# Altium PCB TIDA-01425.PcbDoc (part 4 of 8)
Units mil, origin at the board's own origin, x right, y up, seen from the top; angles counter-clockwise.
Board outline 7000 x 3600 mil, 6 copper layers (Layer 1 - Top Layer, Layer 2 - GND, Layer 3 - Signal / PWR, Layer 4 - Signal / PWR, Layer 5 - PWR, Layer 6 - Bottom Layer), stack 60.4 mil thick; 495 components, 307 nets, 2058 pads, 1870 vias.
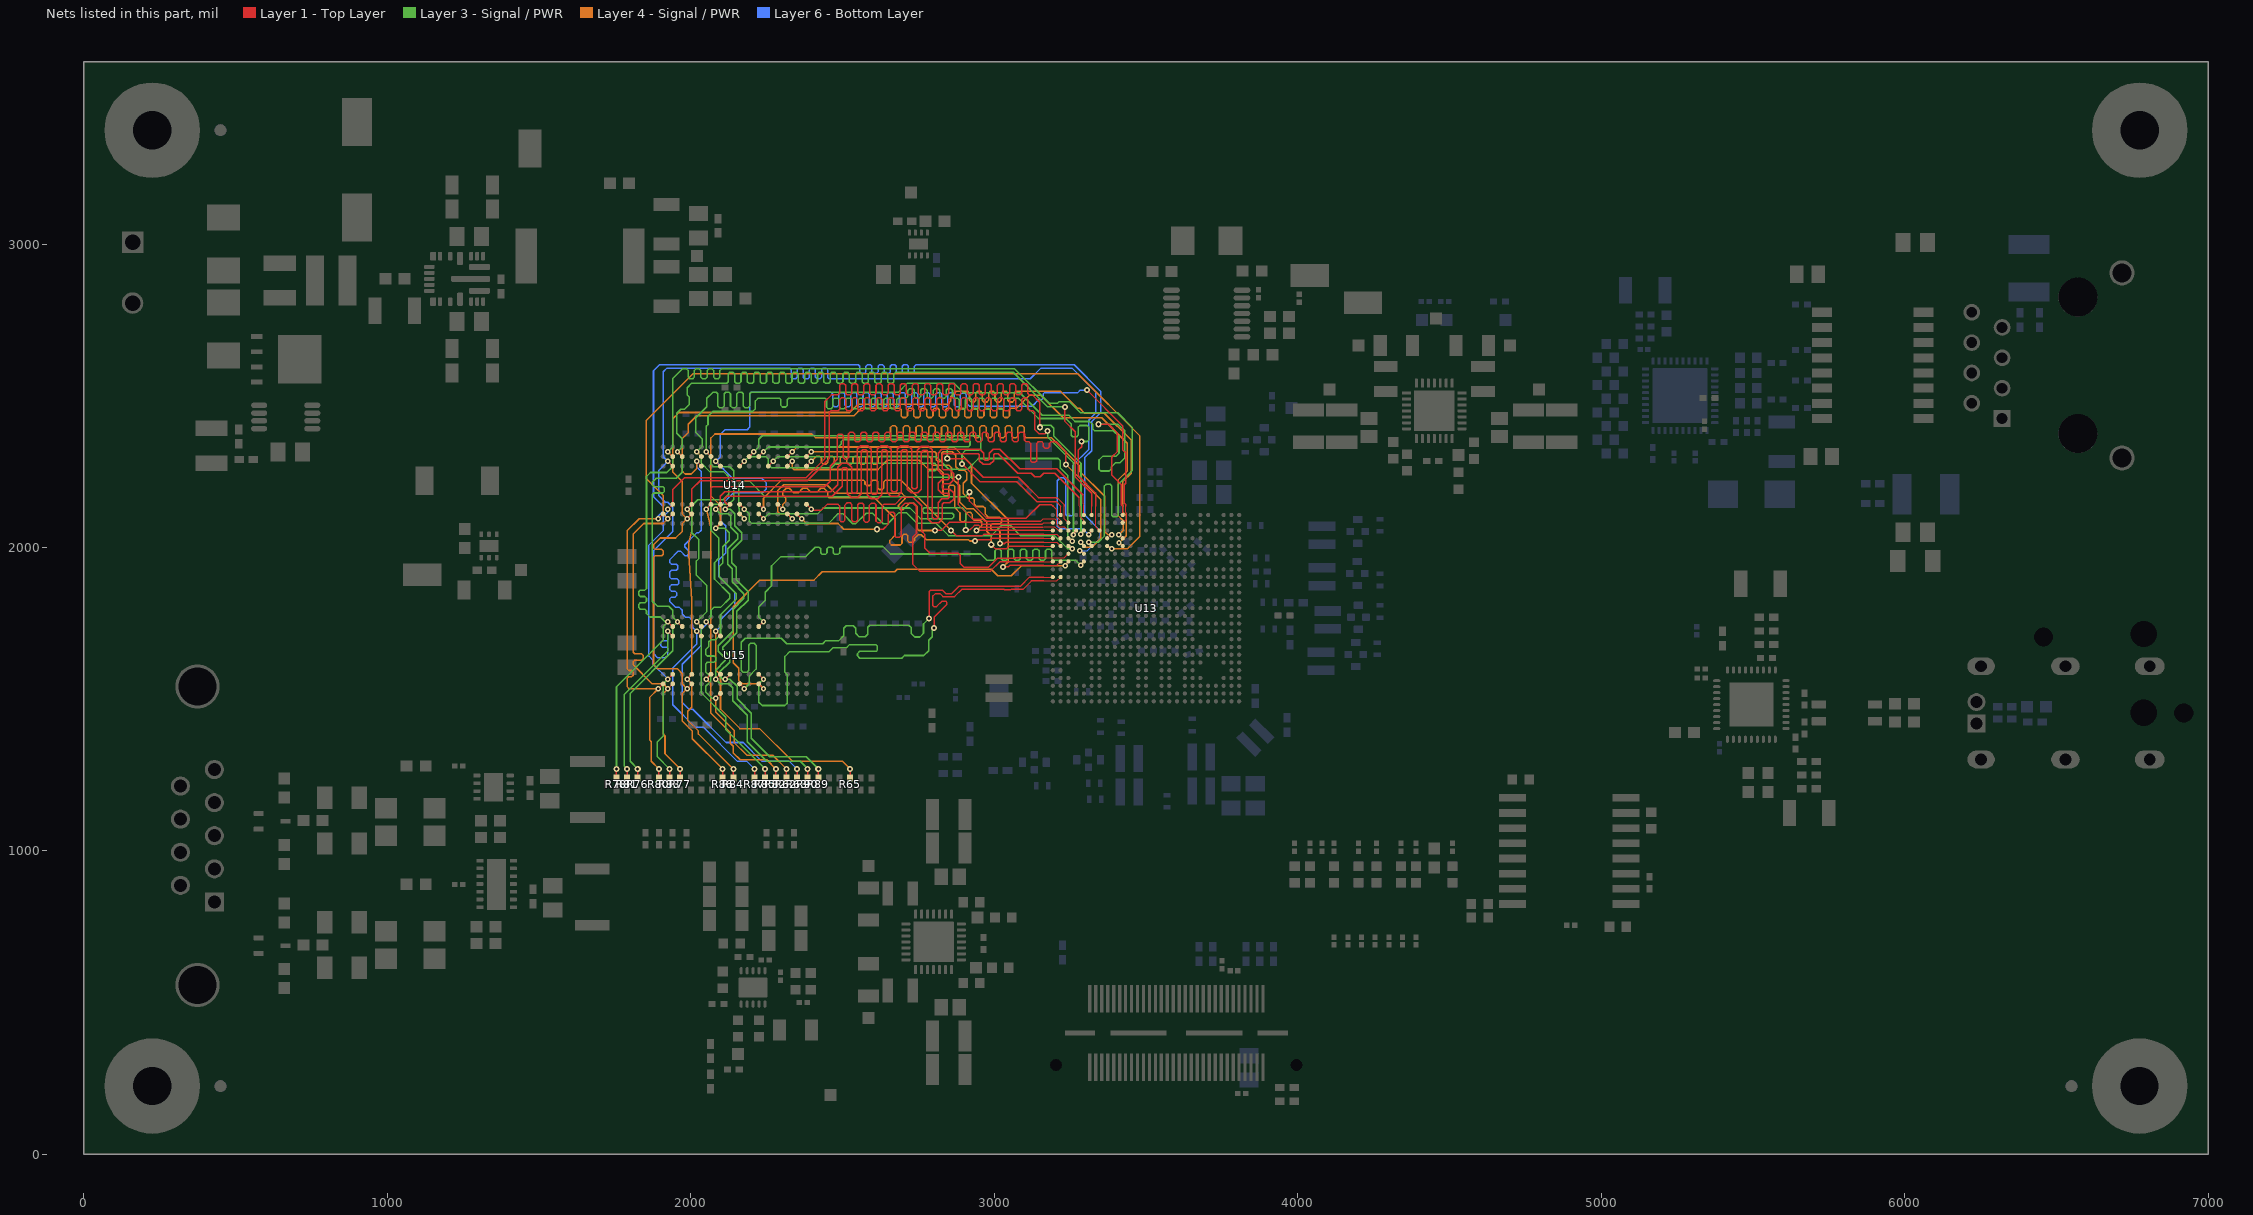
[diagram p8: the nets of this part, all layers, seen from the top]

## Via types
v1: diameter 20, hole 10, Layer 1 - Top Layer to Layer 6 - Bottom Layer, tented both sides, 1119 vias
v2: diameter 20, hole 9.99, Layer 1 - Top Layer to Layer 6 - Bottom Layer, tented both sides, 298 vias
v3: diameter 18, hole 7.99, Layer 1 - Top Layer to Layer 6 - Bottom Layer, tented both sides, 203 vias
v4: diameter 18, hole 8, Layer 1 - Top Layer to Layer 6 - Bottom Layer, tented both sides, 177 vias
v5: diameter 19.68, hole 7.87, Layer 1 - Top Layer to Layer 6 - Bottom Layer, tented both sides, 41 vias
v6: diameter 20, hole 10, Layer 1 - Top Layer to Layer 6 - Bottom Layer, 27 vias
v7: diameter 19.68, hole 7.87, Layer 1 - Top Layer to Layer 6 - Bottom Layer, 5 vias

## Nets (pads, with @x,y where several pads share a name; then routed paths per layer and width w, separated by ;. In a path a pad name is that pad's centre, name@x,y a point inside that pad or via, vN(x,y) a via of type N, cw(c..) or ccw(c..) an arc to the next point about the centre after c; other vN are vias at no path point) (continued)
H_DDR1_A5: R76.1 U13.AE20 U14.P2 U15.P2 | length 4165
  Layer 1 - Top Layer w4: v4(1956.03,1755.22) U15.P2@1971.77,1739.49 ; v4(1956.03,2315.22) U14.P2@1971.77,2299.49 ; U13.AE20@3320.87,2107.09 3320.87,2136
  Layer 1 - Top Layer w5: R76.1@1825,1239.68 v1(1825,1270) ; v1(3233,2463) 3233,2415.5 3267,2381.5 3267,2232.15 3320.87,2178.28 3320.87,2136
  Layer 3 - Signal / PWR w5.25: v1(1825,1270) 1800,1294.99 1800,1519 1940.3,1659.3 1940.3,1739.49 v4(1956.03,1755.22) 1940.3,1770.95 1940.3,1793.06 1927.36,1806 1890,1806 1873,1823 1873,2174.24 1878.25,2179.49 1907.75,2179.49 1913,2184.74 1913,2195.24 1907.75,2200.49 1878.25,2200.49 1873,2205.74 1873,2214.99 1886.01,2228 1952,2228 1971.66,2247.66 1971.66,2279.65 1971.9,2279.89 1971.9,2299.35 v4(1956.03,2315.22) 1971.9,2331.09 1971.9,2358.53 1954,2376.43 1954,2442.17 1967.23,2455.4 1978.92,2455.4 1995.3,2471.78 1995.3,2495 1987.8,2502.5 1987.8,2526.5 2002.1,2540.8 2118.09,2540.8 2123.34,2546.05 2123.34,2571.95 2128.59,2577.2 2139.09,2577.2 2144.34,2571.95 2144.34,2546.05 2149.59,2540.8 2160.09,2540.8 2165.34,2546.05 2165.34,2571.95 2170.59,2577.2 2181.09,2577.2 2186.34,2571.95 2186.34,2546.05 2191.59,2540.8 2202.09,2540.8 2207.34,2546.05 2207.34,2571.95 2212.59,2577.2 2223.09,2577.2 2228.34,2571.95 2228.34,2546.05 2233.59,2540.8 2244.09,2540.8 2249.34,2546.05 2249.34,2571.95 2254.59,2577.2 2265.09,2577.2 2270.34,2571.95 2270.34,2546.05 2275.59,2540.8 2286.09,2540.8 2291.34,2546.05 2291.34,2571.95 2296.59,2577.2 2307.09,2577.2 2312.34,2571.95 2312.34,2546.05 2317.59,2540.8 2328.09,2540.8 2333.34,2546.05 2333.34,2571.95 2338.59,2577.2 2349.09,2577.2 2354.34,2571.95 2354.34,2546.05 2359.59,2540.8 2370.09,2540.8 2375.34,2546.05 2375.34,2571.95 2380.59,2577.2 2391.09,2577.2 2396.34,2571.95 2396.34,2546.05 2401.59,2540.8 2412.09,2540.8 2417.34,2546.05 2417.34,2571.95 2422.59,2577.2 2433.09,2577.2 2438.34,2571.95 2438.34,2546.05 2443.59,2540.8 2454.09,2540.8 2459.34,2546.05 2459.34,2571.95 2464.59,2577.2 2475.09,2577.2 2480.34,2571.95 2480.34,2546.05 2485.59,2540.8 2496.09,2540.8 2501.34,2546.05 2501.34,2571.95 2506.59,2577.2 2517.09,2577.2 2522.34,2571.95 2522.34,2546.05 2527.59,2540.8 2538.09,2540.8 2543.34,2546.05 2543.34,2571.95 2548.59,2577.2 2559.09,2577.2 2564.34,2571.95 2564.34,2546.05 2569.59,2540.8 2580.09,2540.8 2585.34,2546.05 2585.34,2571.95 2590.59,2577.2 2601.09,2577.2 2606.34,2571.95 2606.34,2546.05 2611.59,2540.8 2622.09,2540.8 2627.34,2546.05 2627.34,2571.95 2632.59,2577.2 2643.09,2577.2 2648.34,2571.95 2648.34,2546.05 2653.59,2540.8 2664.09,2540.8 2669.34,2546.05 2669.34,2571.95 2674.59,2577.2 3062.3,2577.2 3176.5,2463 v1(3233,2463)
H_DDR1_A6: R77.1 U13.AA18 U14.R8 U15.R8 | length 3724.2
  Layer 1 - Top Layer w4: v4(1924.54,1534.77) U15.R8@1940.28,1550.51 ; v4(1924.54,2094.77) U14.R8@1940.28,2110.51 ; U13.AA18@3372.05,2004.72 3377.68,2004.72 v3(3386.6,1995.8)
  Layer 1 - Top Layer w5: R77.1@1965,1239.68 v1(1965,1270)
  Layer 4 - Signal / PWR w5.25: v1(1965,1270) 1915,1319.99 1915,1380 1908.8,1386.2 1908.8,1519.03 v4(1924.54,1534.77) 1908.67,1550.64 1899.52,1550.64 1872.37,1550.63 1810,1613 1810,1623.25 1815.25,1628.5 1837.75,1628.5 1843,1633.75 1843,1644.25 1837.75,1649.5 1815.25,1649.5 1810,1654.75 1810,2043.99 1844.9,2078.89 1908.66,2078.89 v4(1924.54,2094.77) 1908.9,2110.41 1908.9,2171.1 1853.1,2226.9 1853.1,2418 2007.23,2572.13 3275.39,2572.13 3480,2367.52 3480,2037 3438.8,1995.8 v3(3386.6,1995.8)
H_DDR1_A7: R78.1 U13.AA20 U14.R2 U15.R2 | length 4115.6
  Layer 1 - Top Layer w4: v4(1924.54,1755.22) U15.R2@1940.28,1739.49 ; v4(1924.54,2315.22) U14.R2@1940.28,2299.49 ; v3(3310.7,2017.2) U13.AA20@3320.8,2004.8
  Layer 1 - Top Layer w5: R78.1@1755,1239.68 v1(1755,1270)
  Layer 3 - Signal / PWR w5.25: v1(1755,1270) 1755,1541 1908.9,1694.9 1908.9,1739.58 v4(1924.54,1755.22) 1915.14,1755.22 1899.51,1770.85 1865.15,1770.85 1854,1782 1854,1791.25 1848.75,1796.5 1833.25,1796.5 1828,1801.75 1828,1812.25 1833.25,1817.5 1848.75,1817.5 1854,1822.75 1854,1833.25 1848.75,1838.5 1833.25,1838.5 1828,1843.75 1828,1854.25 1833.25,1859.5 1848.75,1859.5 1854,1864.75 1854,2234 1867,2247 1920.99,2247 1940.17,2266.18 1940.17,2299.59 v4(1924.54,2315.22) 1940.4,2331.08 1940.4,2557.1 1971.65,2588.35 1985.62,2588.35 1990.87,2583.1 1990.87,2561.45 1996.12,2556.2 2006.62,2556.2 2011.87,2561.45 2011.87,2583.1 2017.12,2588.35 2027.62,2588.35 2032.87,2583.1 2032.87,2561.45 2038.12,2556.2 2048.62,2556.2 2053.87,2561.45 2053.87,2583.1 2059.12,2588.35 2069.62,2588.35 2074.87,2583.1 2074.87,2561.45 2080.12,2556.2 2090.62,2556.2 2095.87,2561.45 2095.87,2583.1 2101.12,2588.35 3067.85,2588.35 3180.9,2475.3 3208.1,2475.3 3213.2,2480.4 3247.6,2480.4 3284.4,2443.6 3407.19,2443.6 3454.1,2396.69 3454.1,2253 3408.4,2207.3 3408.4,2105.4 3403.7,2100.7 3392.45,2100.7 3387.2,2105.95 3387.2,2202.7 3381.9,2208 3368.6,2208 3363,2202.4 3363,2037.5 3342.7,2017.2 v3(3310.7,2017.2)
H_DDR1_A8: R80.1 U13.Y21 U14.T8 U15.T8 | length 4009.1
  Layer 1 - Top Layer w4: v4(1893.04,1534.77) U15.T8@1908.78,1550.51 ; v4(1893.04,2094.77) U14.T8@1908.78,2110.51 ; v3(3282.2,1988.7) U13.Y21@3295.2,1979.2
  Layer 1 - Top Layer w5: R80.1@1895,1239.68 v1(1895,1270)
  Layer 4 - Signal / PWR w5.25: v4(1893.04,2094.77) 1829.76,2094.77 1790,2055.01 1790,1599.76 1795.25,1594.51 1804.75,1594.51 1810,1589.26 1810,1578.76 1804.75,1573.51 1795.25,1573.51 1790,1568.26 1790,1542.01 1797.24,1534.77 v4(1893.04,1534.77) 1864.13,1505.86 1864.13,1365.87 1870,1360 1870,1294.99 v1(1895,1270)
  Layer 6 - Bottom Layer w4: v3(3282.2,1988.7) 3306.7,1988.7 3348.79,2030.79 3348.79,2056.21
  Layer 6 - Bottom Layer w5: v4(1893.04,2094.77) 1893.04,2104.33 1908.54,2119.83 1908.54,2135.46 1877,2167 1877,2582.4 1896.5,2601.9 2551.93,2601.9 2556.93,2596.9 2556.93,2578.4 2561.93,2573.4 2571.93,2573.4 2576.93,2578.4 2576.93,2596.9 2581.93,2601.9 2591.93,2601.9 2596.93,2596.9 2596.93,2578.4 2601.93,2573.4 2611.93,2573.4 2616.93,2578.4 2616.93,2596.9 2621.93,2601.9 2631.93,2601.9 2636.93,2596.9 2636.93,2578.4 2641.93,2573.4 2651.93,2573.4 2656.93,2578.4 2656.93,2596.9 2661.93,2601.9 2671.93,2601.9 2676.93,2596.9 2676.93,2578.4 2681.93,2573.4 2691.93,2573.4 2696.93,2578.4 2696.93,2596.9 2701.93,2601.9 2711.93,2601.9 2716.93,2596.9 2716.93,2578.4 2721.93,2573.4 2731.93,2573.4 2736.93,2578.4 2736.93,2596.9 2741.93,2601.9 3263.4,2601.9 3351,2514.3 3351,2445 3321,2415 3321,2319 3298,2296 3298,2107 3348.79,2056.21
H_DDR1_A9: R81.1 U13.AC20 U14.R3 U15.R3 | length 4335.4
  Layer 1 - Top Layer w4: v4(1924.54,1723.73) U15.R3@1940.28,1707.99 ; v4(1924.54,2283.73) U14.R3@1940.28,2267.99 ; v3(3310.8,2042.6) U13.AC20@3320.87,2055.91
  Layer 1 - Top Layer w5: R81.1@1790,1239.68 v1(1790,1270)
  Layer 3 - Signal / PWR w5.25: v1(1790,1270) 1780,1279.99 1780,1514.6 1924.54,1659.14 v4(1924.54,1723.73)
  Layer 6 - Bottom Layer w5: v4(1924.54,1723.73) 1924.54,1696.87 1919.54,1691.87 1906,1691.87 1901,1686.87 1901,1676.87 1906,1671.87 1919.54,1671.87 1924.54,1666.87 1924.54,1645.54 1915.81,1636.81 1890.19,1636.81 1877.54,1649.46 1877.54,1780.29 1877.53,1989.53 1940.04,2052.04 1940.04,2132.69 1923.73,2149 1915.99,2149 1894,2170.99 1894,2253.19 v4(1924.54,2283.73) 1909.04,2299.23 1909.04,2578.94 1921.1,2591 2325.69,2591 2330.69,2586 2330.69,2560.7 2335.69,2555.7 2345.69,2555.7 2350.69,2560.7 2350.69,2586 2355.69,2591 2365.69,2591 2370.69,2586 2370.69,2560.7 2375.69,2555.7 2385.69,2555.7 2390.69,2560.7 2390.69,2586 2395.69,2591 2405.69,2591 2410.69,2586 2410.69,2560.7 2415.69,2555.7 2425.69,2555.7 2430.69,2560.7 2430.69,2586 2435.69,2591 2445.69,2591 2450.69,2586 2450.69,2560.7 2455.69,2555.7 3118.7,2555.7 3154,2591 3256.34,2591 3334,2513.34 3334,2442.15 3311,2419.15 3311,2323.15 3259.1,2271.25 3259.1,2109.11 3254.09,2104.1 3239.31,2104.1 3235.3,2108.11 3235.3,2222.6 3228.3,2229.6 3217.6,2229.6 3207.8,2219.8 3207.8,2070.1 3215.55,2062.35 3291.05,2062.35 v3(3310.8,2042.6)
H_DDR1_A10: R82.1 U13.AA21 U14.L7 U15.L7 | length 3973.1
  Layer 1 - Top Layer w4: v4(2050.52,1566.26) U15.L7@2066.26,1582.01 ; v4(2050.52,2126.26) U14.L7@2066.26,2142.01 ; v3(3284.4,2016.8) 3285.2,2016.8 3295.2,2006.8 U13.AA21@3295.2,2004.8
  Layer 1 - Top Layer w5: U14.L7@2066.26,2142.01 2066.26,2194.96 2071.3,2200 2441,2200 2459.25,2218.25 2459.25,2267.45 2482.75,2290.95 2482.75,2368.6 2487.75,2373.6 2497.5,2373.6 2502.1,2369 2502.1,2333.5 2502.2,2333.4 2502.2,2296.5 2507.46,2291.24 2514.54,2291.24 2519.62,2296.32 2519.62,2374.9 2524.62,2379.9 2534.62,2379.9 2539.62,2374.9 2539.62,2353 2544.62,2348 2554.62,2348 2559.62,2353 2559.62,2374.9 2564.62,2379.9 2574.62,2379.9 2579.62,2374.9 2579.62,2353 2584.62,2348 2594.62,2348 2599.62,2353 2599.62,2374.9 2604.62,2379.9 2614.62,2379.9 2619.62,2374.9 2619.62,2353 2624.62,2348 2634.62,2348 2639.62,2353 2639.62,2374.9 2644.62,2379.9 2654.62,2379.9 2659.62,2374.9 2659.62,2353 2664.62,2348 2674.62,2348 2679.62,2353 2679.62,2374.9 2684.62,2379.9 2694.62,2379.9 2699.62,2374.9 2699.62,2353 2704.62,2348 2714.62,2348 2719.62,2353 2719.62,2374.9 2724.62,2379.9 2734.62,2379.9 2739.62,2374.9 2739.62,2353 2744.62,2348 2754.62,2348 2759.62,2353 2759.62,2374.9 2764.62,2379.9 2774.62,2379.9 2779.62,2374.9 2779.62,2353 2784.62,2348 2794.62,2348 2799.62,2353 2799.62,2374.9 2804.62,2379.9 2814.62,2379.9 2819.62,2374.9 2819.62,2353 2824.62,2348 2834.62,2348 2839.62,2353 2839.62,2374.9 2844.62,2379.9 2854.62,2379.9 2859.62,2374.9 2859.62,2353 2864.62,2348 2874.62,2348 2879.62,2353 2879.62,2374.9 2884.62,2379.9 2894.62,2379.9 2899.62,2374.9 2899.62,2353 2904.62,2348 2914.62,2348 2919.62,2353 2919.62,2374.9 2924.62,2379.9 2934.62,2379.9 2939.62,2374.9 2939.62,2353 2944.62,2348 2954.62,2348 2959.62,2353 2959.62,2374.9 2964.62,2379.9 2974.62,2379.9 2979.62,2374.9 2979.62,2353 2984.62,2348 2994.62,2348 2999.62,2353 2999.62,2374.9 3004.62,2379.9 3014.62,2379.9 3019.62,2374.9 3019.62,2353 3024.62,2348 3034.62,2348 3039.62,2353 3039.62,2374.9 3044.62,2379.9 3054.62,2379.9 3059.62,2374.9 3059.62,2353 3064.62,2348 3074.62,2348 3079.62,2353 3079.62,2374.9 3084.62,2379.9 3094.62,2379.9 3099.62,2374.9 3099.62,2353 3104.62,2348 3114.62,2348 3119.62,2343 3119.62,2285.9 3124.62,2280.9 3134.62,2280.9 3139.62,2285.9 3139.62,2343 3144.62,2348 3156.97,2348 3161.97,2343 3161.97,2332 3166.97,2327 3176.97,2327 3181.97,2332 3181.97,2343 3186.97,2348 3204,2348 3236,2316 v1(3236,2273) ; R82.1@2280,1239.68 v1(2280,1270)
  Layer 4 - Signal / PWR w5.25: v4(2050.52,2126.26) 2066.2,2068.76 2066.2,1581.94 v4(2050.52,1566.26) 2066.3,1550.48 2066.3,1453.7 2130,1390 2130,1355 2140,1345 2140,1322.5 2162.5,1300 2250,1300 v1(2280,1270) ; v1(3236,2273) 3351.1,2157.9 3351.1,2030.3 3321.9,2001.1 3300.1,2001.1 v3(3284.4,2016.8)
H_DDR1_A11: R83.1 U13.AC21 U14.R7 U15.R7 | length 4038.6
  Layer 1 - Top Layer w4: v4(1924.54,1566.26) U15.R7@1940.28,1582.01 ; v4(1924.54,2126.26) U14.R7@1940.28,2142.01 ; v3(3285.64,2043.02) U13.AC21@3295.28,2055.91
  Layer 1 - Top Layer w5: R83.1@1930,1239.68 v1(1930,1270) ; U14.R7@1940.28,2142.01 1940.28,2191.28 1979,2230 2379.32,2230 2440.9,2291.58 2440.9,2480.4 2463.3,2502.8 2485.22,2502.8 2490.22,2507.8 2490.22,2534.2 2495.22,2539.2 2505.22,2539.2 2510.22,2534.2 2510.22,2507.8 2515.22,2502.8 2525.22,2502.8 2530.22,2507.8 2530.22,2534.2 2535.22,2539.2 2545.22,2539.2 2550.22,2534.2 2550.22,2507.8 2555.22,2502.8 2565.22,2502.8 2570.22,2507.8 2570.22,2534.2 2575.22,2539.2 2585.22,2539.2 2590.22,2534.2 2590.22,2507.8 2595.22,2502.8 2605.22,2502.8 2610.22,2507.8 2610.22,2534.2 2615.22,2539.2 2625.22,2539.2 2630.22,2534.2 2630.22,2507.8 2635.22,2502.8 2645.22,2502.8 2650.22,2507.8 2650.22,2534.2 2655.22,2539.2 2665.22,2539.2 2670.22,2534.2 2670.22,2507.8 2675.22,2502.8 2685.22,2502.8 2690.22,2507.8 2690.22,2534.2 2695.22,2539.2 2705.22,2539.2 2710.22,2534.2 2710.22,2507.8 2715.22,2502.8 2725.22,2502.8 2730.22,2507.8 2730.22,2534.2 2735.22,2539.2 2745.22,2539.2 2750.22,2534.2 2750.22,2507.8 2755.22,2502.8 2765.22,2502.8 2770.22,2507.8 2770.22,2534.2 2775.22,2539.2 2785.22,2539.2 2790.22,2534.2 2790.22,2507.8 2795.22,2502.8 2805.22,2502.8 2810.22,2507.8 2810.22,2534.2 2815.22,2539.2 2825.22,2539.2 2830.22,2534.2 2830.22,2507.8 2835.22,2502.8 2845.22,2502.8 2850.22,2507.8 2850.22,2534.2 2855.22,2539.2 2865.22,2539.2 2870.22,2534.2 2870.22,2507.8 2875.22,2502.8 2885.22,2502.8 2890.22,2507.8 2890.22,2534.2 2895.22,2539.2 2905.22,2539.2 2910.22,2534.2 2910.22,2507.8 2915.22,2502.8 2925.22,2502.8 2930.22,2507.8 2930.22,2534.2 2935.22,2539.2 2945.22,2539.2 2950.22,2534.2 2950.22,2507.8 2955.22,2502.8 2965.22,2502.8 2970.22,2507.8 2970.22,2534.2 2975.22,2539.2 2985.22,2539.2 2990.22,2534.2 2990.22,2507.8 2995.22,2502.8 3005.22,2502.8 3010.22,2507.8 3010.22,2534.2 3015.22,2539.2 3025.22,2539.2 3030.22,2534.2 3030.22,2507.8 3035.22,2502.8 3045.22,2502.8 3050.22,2507.8 3050.22,2534.2 3055.22,2539.2 3065.22,2539.2 3070.22,2534.2 3070.22,2507.8 3075.22,2502.8 3085.22,2502.8 3090.22,2507.8 3090.22,2534.2 3095.22,2539.2 3105.22,2539.2 3110.22,2534.2 3110.22,2507.8 3115.22,2502.8 3125.7,2502.8 3150,2478.5 v1(3150,2396)
  Layer 3 - Signal / PWR w5.25: v4(1924.54,1566.26) 1908.7,1550.42 1908.7,1378.7 1890,1360 1890,1309.99 v1(1930,1270) ; v1(3150,2396) 3157,2403 3186,2403 3196,2393 3196,2367 3285.64,2277.36 v3(3285.64,2043.02)
  Layer 6 - Bottom Layer w5: v4(1924.54,1566.26) 1874,1616.8 1874,1630 1862,1642 1862,2008 1908.54,2054.54 1908.54,2099 1909.04,2099.5 1909.04,2101.2 1924.54,2116.7 v4(1924.54,2126.26)
H_DDR1_A12: R84.1 U13.AC22 U14.N7 U15.N7 | length 4051.6
  Layer 1 - Top Layer w4: v4(1987.53,1566.26) U15.N7@2003.27,1582.01 ; v3(3260.97,2042.53) U13.AC22@3269.59,2055.97
  Layer 1 - Top Layer w5: v4(1987.53,2126.26) U14.N7@2003.27,2142.01 2003.27,2192.27 2031,2220 2383.48,2220 2456.44,2292.96 2456.44,2445.34 2461.9,2450.8 2485.69,2450.8 2490.69,2455.8 2490.69,2487.7 2495.69,2492.7 2505.69,2492.7 2510.69,2487.7 2510.69,2455.8 2515.69,2450.8 2525.69,2450.8 2530.69,2455.8 2530.69,2487.7 2535.69,2492.7 2545.69,2492.7 2550.69,2487.7 2550.69,2455.8 2555.69,2450.8 2565.69,2450.8 2570.69,2455.8 2570.69,2487.7 2575.69,2492.7 2585.69,2492.7 2590.69,2487.7 2590.69,2455.8 2595.69,2450.8 2605.69,2450.8 2610.69,2455.8 2610.69,2487.7 2615.69,2492.7 2625.69,2492.7 2630.69,2487.7 2630.69,2455.8 2635.69,2450.8 2645.69,2450.8 2650.69,2455.8 2650.69,2487.7 2655.69,2492.7 2665.69,2492.7 2670.69,2487.7 2670.69,2455.8 2675.69,2450.8 2685.69,2450.8 2690.69,2455.8 2690.69,2487.7 2695.69,2492.7 2705.69,2492.7 2710.69,2487.7 2710.69,2455.8 2715.69,2450.8 2725.69,2450.8 2730.69,2455.8 2730.69,2487.7 2735.69,2492.7 2745.69,2492.7 2750.69,2487.7 2750.69,2455.8 2755.69,2450.8 2765.69,2450.8 2770.69,2455.8 2770.69,2487.7 2775.69,2492.7 2785.69,2492.7 2790.69,2487.7 2790.69,2455.8 2795.69,2450.8 2805.69,2450.8 2810.69,2455.8 2810.69,2487.7 2815.69,2492.7 2825.69,2492.7 2830.69,2487.7 2830.69,2455.8 2835.69,2450.8 2845.69,2450.8 2850.69,2455.8 2850.69,2487.7 2855.69,2492.7 2865.69,2492.7 2870.69,2487.7 2870.69,2455.8 2875.69,2450.8 2885.69,2450.8 2890.69,2455.8 2890.69,2487.7 2895.69,2492.7 2905.69,2492.7 2910.69,2487.7 2910.69,2455.8 2915.69,2450.8 2925.69,2450.8 2930.69,2455.8 2930.69,2487.7 2935.69,2492.7 2945.69,2492.7 2950.69,2487.7 2950.69,2455.8 2955.69,2450.8 2965.69,2450.8 2970.69,2455.8 2970.69,2487.7 2975.69,2492.7 2985.69,2492.7 2990.69,2487.7 2990.69,2455.8 2995.69,2450.8 3005.69,2450.8 3010.69,2455.8 3010.69,2487.7 3015.69,2492.7 3025.69,2492.7 3030.69,2487.7 3030.69,2455.8 3035.69,2450.8 3045.69,2450.8 3050.69,2455.8 3050.69,2487.7 3055.69,2492.7 3065.69,2492.7 3070.69,2487.7 3070.69,2455.8 3075.69,2450.8 3085.69,2450.8 3090.69,2455.8 3090.69,2487.7 3095.69,2492.7 3105.69,2492.7 3110.69,2487.7 3110.69,2455.8 3115.69,2450.8 3127.6,2450.8 3133.5,2444.9 3133.5,2388.5 3147,2375 3167,2375 v1(3176,2384) ; R84.1@2140,1239.68 v1(2140,1270)
  Layer 3 - Signal / PWR w5.25: v1(3176,2384) 3176,2364 3260.97,2279.03 v3(3260.97,2042.53)
  Layer 4 - Signal / PWR w5.25: v4(1987.53,2126.26) 2003.2,2101.94 2003.2,2053.81 1992.5,2013.79 1992.5,1977.8 2003.2,1826.9 2003.2,1581.93 v4(1987.53,1566.26) 2003.2,1550.59 2003.2,1473.2 1990,1460 1990,1430 2025,1395 2025,1384.99 v1(2140,1270)
H_DDR1_BA0: R85.1 U13.AE16 U14.M2 U15.M2 | length 4182.8
  Layer 1 - Top Layer w4: v4(2019.02,1755.22) U15.M2@2034.76,1739.49 ; v4(2019.02,2315.22) U14.M2@2034.76,2299.49 ; U13.AE16@3423.23,2107.09 3423.23,2136
  Layer 1 - Top Layer w5: R85.1@2245,1239.68 v1(2245,1270) ; v1(3343,2406) 3377,2406 3406,2377 3406,2316 3387,2297 3387,2239 3418.5,2207.5 3418.5,2197.31 3418.49,2140.74 3423.23,2136
  Layer 3 - Signal / PWR w5.25: v1(2245,1270) 2115,1399.99 2115,1440 2034.8,1520.2 2034.8,1739.44 v4(2019.02,1755.22) 2053,1789.2 2053,1873.48 2018.37,1908.11 2018.37,1955.37 2026.63,1963.63 2026.63,2025.37 2003.16,2048.84 2003.16,2137.16 2023,2157 2107,2157 2125,2175 2125,2233.01 2109.01,2249 2063.15,2249 2034.89,2277.26 2034.89,2299.35 v4(2019.02,2315.22) 2038.1,2334.3 2038.1,2357 2016,2379.1 2016,2427 2052.8,2463.8 2052.8,2491.3 2072.9,2511.4 2083.57,2511.4 2088.82,2506.15 2088.82,2466.25 2094.07,2461 2104.57,2461 2109.82,2466.25 2109.82,2506.15 2115.07,2511.4 2125.57,2511.4 2130.82,2506.15 2130.82,2466.25 2136.07,2461 2146.57,2461 2151.82,2466.25 2151.82,2506.15 2157.07,2511.4 2167.57,2511.4 2172.82,2506.15 2172.82,2466.25 2178.07,2461 2188.57,2461 2193.82,2466.25 2193.82,2506.15 2199.07,2511.4 2684,2511.4 2714.3,2541.7 2866.3,2541.7 2898.5,2509.5 3083.7,2509.5 3157.9,2435.3 3245.93,2435.3 3266.11,2415.12 3313.88,2415.12 3325,2404 3325,2390.25 3330.25,2385 3392,2385 3411,2366 3411,2310 3402,2301 3358,2301 3345.22,2288.22 3345.22,2257.26 3350.48,2252 3379,2252 3386,2259 3386,2266 3398.63,2278.63 3413.63,2278.63 3429.75,2294.75 3429.75,2384.25 3408,2406 v1(3343,2406)
H_DDR1_BA1: R86.1 U13.AA16 U14.N8 U15.N8 | length 3756.7
  Layer 1 - Top Layer w4: v4(1987.53,1534.77) U15.N8@2003.27,1550.51 ; v3(3411,2014.8) U13.AA16@3423.23,2004.72
  Layer 1 - Top Layer w5: v4(1987.53,2094.77) U14.N8@2003.27,2110.51 ; R86.1@2105,1239.68 v1(2105,1270)
  Layer 4 - Signal / PWR w5.25: v1(2105,1270) 2005,1369.99 2005,1395 1971.7,1428.3 1971.7,1518.94 v4(1987.53,1534.77) 1971.9,1550.4 1971.9,1584.1 1956,1600 1890.01,1600 1877,1613.01 1877,1967.25 1882.25,1972.5 1903.75,1972.5 1909,1977.75 1909,1988.25 1903.75,1993.5 1882.25,1993.5 1877,1998.75 1877,2009 1899,2031 1949.77,2031 1971.66,2052.89 1971.66,2078.9 v4(1987.53,2094.77) 1971.9,2110.4 1971.9,2217.1 1940.17,2248.83 1940.17,2424.17 1960.65,2444.65 2524.15,2444.65 2551.9,2472.4 2599.08,2472.4 2599.23,2472.25 2846.55,2472.25 2857,2482.7 2857,2496.6 2874.8,2514.4 2913.01,2514.4 2918.26,2509.15 2918.26,2484.65 2923.51,2479.4 2934.01,2479.4 2939.26,2484.65 2939.26,2509.15 2944.51,2514.4 2955.01,2514.4 2960.26,2509.15 2960.26,2484.65 2965.51,2479.4 2976.01,2479.4 2981.26,2484.65 2981.26,2509.15 2986.51,2514.4 2997.01,2514.4 3002.26,2509.15 3002.26,2484.65 3007.51,2479.4 3018.01,2479.4 3023.26,2484.65 3023.26,2509.15 3028.51,2514.4 3039.01,2514.4 3044.26,2509.15 3044.26,2484.65 3049.51,2479.4 3060.01,2479.4 3065.26,2484.65 3065.26,2509.15 3070.51,2514.4 3218.2,2514.4 3274.1,2458.5 3281.49,2458.5 3297.39,2442.6 3362.7,2442.6 3451.3,2354 3451.3,2244.8 3424,2217.5 3424,2116.4 3434.7,2105.7 3434.7,2038.5 v3(3411,2014.8)
H_DDR1_BA2: R87.1 U13.AB16 U14.M3 U15.M3 | length 4123.5
  Layer 1 - Top Layer w4: v4(2019.02,1723.73) U15.M3@2034.76,1707.99 ; v4(2019.02,2283.73) U14.M3@2034.76,2267.99 ; v3(3409.9,2041.4) U13.AB16@3423.23,2030.32
  Layer 1 - Top Layer w5: R87.1@2210,1239.68 v1(2210,1270)
  Layer 4 - Signal / PWR w5.25: v4(2019.02,2283.73) 2019.02,2259.63 2001.39,2242 1980.99,2242 1971.9,2251.09 1971.9,2358.9 1991.7,2378.7 1991.7,2406.21 2019.89,2434.4 2537.5,2434.4 2562,2458.9 2687.78,2458.9 2693.03,2453.65 2693.03,2433.45 2698.28,2428.2 2708.78,2428.2 2714.03,2433.45 2714.03,2453.65 2719.28,2458.9 2729.78,2458.9 2735.03,2453.65 2735.03,2433.45 2740.28,2428.2 2750.78,2428.2 2756.03,2433.45 2756.03,2453.65 2761.28,2458.9 2771.78,2458.9 2777.03,2453.65 2777.03,2433.45 2782.28,2428.2 2792.78,2428.2 2798.03,2433.45 2798.03,2453.65 2803.28,2458.9 2813.78,2458.9 2819.03,2453.65 2819.03,2433.45 2824.28,2428.2 2834.78,2428.2 2840.03,2433.45 2840.03,2453.65 2845.28,2458.9 2855.78,2458.9 2861.03,2453.65 2861.03,2433.45 2866.28,2428.2 2876.78,2428.2 2882.03,2433.45 2882.03,2453.65 2887.28,2458.9 2897.78,2458.9 2903.03,2453.65 2903.03,2433.45 2908.28,2428.2 2918.78,2428.2 2924.03,2433.45 2924.03,2453.65 2929.28,2458.9 2939.78,2458.9 2945.03,2453.65 2945.03,2433.45 2950.28,2428.2 2960.78,2428.2 2966.03,2433.45 2966.03,2453.65 2971.28,2458.9 2981.78,2458.9 2987.03,2453.65 2987.03,2433.45 2992.28,2428.2 3002.78,2428.2 3008.03,2433.45 3008.03,2453.65 3013.28,2458.9 3023.78,2458.9 3029.03,2453.65 3029.03,2433.45 3034.28,2428.2 3044.78,2428.2 3050.03,2433.45 3050.03,2453.65 3055.28,2458.9 3073,2458.9 3115,2500.9 3153.2,2500.9 3226.9,2427.2 3353.9,2427.2 3437.8,2343.3 3437.8,2251.8 3408,2222 3408,2105 3425.4,2087.6 3425.4,2056.9 v3(3409.9,2041.4)
  Layer 6 - Bottom Layer w5: v4(2019.02,2283.73) 2019.02,2265.97 2034.52,2250.47 2034.52,2056.84 2025.45,2047.77 2018.76,2047.77 1980.04,2009.05 1980.04,2001.99 1994.99,1987.05 1994.99,1979.99 1987.9,1972.9 1980.84,1972.9 1965.89,1987.84 1958.83,1987.84 1931,1960.01 1931,1950.01 1936,1945.01 1952,1945.01 1957,1940.01 1957,1930.01 1952,1925.01 1936,1925.01 1931,1920.01 1931,1901.31 1936,1896.31 1955,1896.31 1960,1891.31 1960,1881.31 1955,1876.31 1936,1876.31 1931,1871.31 1931,1861.31 1936,1856.31 1948,1856.31 1953,1851.31 1953,1841.31 1948,1836.31 1936,1836.31 1931,1831.31 1931,1821.31 1950.09,1802.22 1962.46,1802.22 1971.53,1793.15 1971.53,1780.78 1981.59,1770.72 1993.96,1770.72 2003.03,1761.65 2003.03,1749.28 2004,1748.31 2004,1738.75 v4(2019.02,1723.73) 2019.02,1681 1940.53,1602.51 1940.53,1481.47 2014,1408 2041,1408 2154,1295 2185,1295 v1(2210,1270)
H_DDR1_CASN: R65.2 U13.AD16 U14.K3 U15.K3 | length 4588.2
  Layer 1 - Top Layer w4: v4(2082.02,1723.73) U15.K3@2097.76,1707.99 ; v4(2082.02,2283.73) U14.K3@2097.76,2267.99 ; U13.AD16@3423.23,2081.5 3435.92,2094.19 3435.92,2114.08 3433.23,2116.77 3433.23,2136
  Layer 1 - Top Layer w5: R65.2@2525,1239.69 v1(2525,1270) ; v1(3305.5,2518.5) 3423,2401 3423,2321.99 3433.23,2311.76 3433.23,2246.37 3433.24,2238.08 ; 3433.23,2136 3433.23,2141.77 3428.5,2146.5 3428.5,2206.84 3433.23,2211.57 3433.23,2238.07
  Layer 4 - Signal / PWR w5.25: v4(2082.02,1723.73) 2082.02,1595.98 2097.7,1580.3 2097.7,1467.3 2161.8,1403.2 2226.6,1403.2 2334.8,1295 2500,1295 v1(2525,1270)
  Layer 6 - Bottom Layer w5: v4(2082.02,1723.73) 2098.01,1739.72 2098.01,1761.65 2144,1807.64 2144,1853.01 2092,1905.01 2092,1958.99 2115,1981.99 2115,2071.36 2107.09,2079.27 2098.01,2088.34 2098.01,2137.01 2141,2180 2236,2180 2248,2192 2248,2214 2234,2228 2137.75,2228 v4(2082.02,2283.73) 2097.52,2299.23 2097.52,2373.22 2112.5,2388.2 2186.1,2388.2 2194.45,2396.55 2194.45,2506.83 2199.45,2511.83 2461.05,2511.83 2467.4,2505.48 2467.4,2469.3 2472.4,2464.3 2482.4,2464.3 2487.4,2469.3 2487.4,2505.48 2492.4,2510.48 2502.4,2510.48 2507.4,2505.48 2507.4,2469.3 2512.4,2464.3 2522.4,2464.3 2527.4,2469.3 2527.4,2505.48 2532.4,2510.48 2542.4,2510.48 2547.4,2505.48 2547.4,2469.3 2552.4,2464.3 2562.4,2464.3 2567.4,2469.3 2567.4,2505.48 2572.4,2510.48 2582.4,2510.48 2587.4,2505.48 2587.4,2469.3 2592.4,2464.3 2602.4,2464.3 2607.4,2469.3 2607.4,2505.48 2612.4,2510.48 2622.4,2510.48 2627.4,2505.48 2627.4,2469.3 2632.4,2464.3 2642.4,2464.3 2647.4,2469.3 2647.4,2505.48 2652.4,2510.48 2662.4,2510.48 2667.4,2505.48 2667.4,2469.3 2672.4,2464.3 2682.4,2464.3 2687.4,2469.3 2687.4,2505.48 2692.4,2510.48 2702.4,2510.48 2707.4,2505.48 2707.4,2469.3 2712.4,2464.3 2722.4,2464.3 2727.4,2469.3 2727.4,2505.48 2732.4,2510.48 2742.4,2510.48 2747.4,2505.48 2747.4,2469.3 2752.4,2464.3 2762.4,2464.3 2767.4,2469.3 2767.4,2505.48 2772.4,2510.48 2782.4,2510.48 2787.4,2505.48 2787.4,2469.3 2792.4,2464.3 2802.4,2464.3 2807.4,2469.3 2807.4,2505.48 2812.4,2510.48 2822.4,2510.48 2827.4,2505.48 2827.4,2469.3 2832.4,2464.3 2842.4,2464.3 2847.4,2469.3 2847.4,2505.48 2852.4,2510.48 2862.4,2510.48 2867.4,2505.48 2867.4,2469.3 2872.4,2464.3 2882.4,2464.3 2887.4,2469.3 2887.4,2502.7 2892.4,2507.7 2903.3,2507.7 2908.3,2502.7 2908.3,2475.3 2918.2,2465.4 3124.86,2465.4 3145.96,2486.5 3155.96,2486.5 3160.96,2491.5 3160.96,2505.48 3165.96,2510.48 3275.48,2510.48 3283.5,2518.5 v1(3305.5,2518.5)
H_DDR1_CKE: R62.1 U13.AB18 U14.K9 U15.K9 | length 3811.3
  Layer 1 - Top Layer w4: v4(2082.02,1503.27) U15.K9@2097.76,1519.02 ; v4(2082.02,2063.27) U14.K9@2097.76,2079.02 ; U13.AB18@3372.05,2030.31 v3(3386.6,2042.5)
  Layer 1 - Top Layer w5: R62.1@2315,1239.68 v1(2315,1270)
  Layer 3 - Signal / PWR w5.25: v4(2082.02,1503.27) 2069.74,1503.27 2049,1524.01 2049,1542.64 2066.15,1559.79 2066.15,1572.73 2049,1589.88 2049,1616.01 2054.25,1621.26 2076.58,1621.26 2081.83,1626.51 2081.83,1637.01 2076.58,1642.26 2054.25,1642.26 2049,1647.51 2049,1663.7 2059.04,1673.74 2059.04,1681.16 2058.81,1681.39 2058.81,1688.81 2066.24,1696.24 2073.66,1696.24 2073.89,1696.01 2081.31,1696.01 2097.88,1712.58 2097.88,1777.88 2150,1830 2150,1847.01 2094,1903.01 2094,1938 2105,1949 2105,2002 2126.28,2023.28 2126.28,2048.72 2111.73,2063.27 v4(2082.02,2063.27)
  Layer 4 - Signal / PWR w5.25: v4(2082.02,1503.27) 2082.02,1457.98 2142.5,1397.5 2142.5,1357.5 2185,1315 2270,1315 v1(2315,1270) ; v4(2082.02,2063.27) 2097.7,2078.95 2097.7,2138.3 2066.2,2169.8 2066.2,2360.69 2079.51,2374 2398.7,2374 2410.6,2362.1 2652.69,2362.1 2657.94,2367.35 2657.94,2395.15 2663.19,2400.4 2673.69,2400.4 2678.94,2395.15 2678.94,2367.35 2684.19,2362.1 2694.69,2362.1 2699.94,2367.35 2699.94,2395.15 2705.19,2400.4 2715.69,2400.4 2720.94,2395.15 2720.94,2367.35 2726.19,2362.1 2736.69,2362.1 2741.94,2367.35 2741.94,2395.15 2747.19,2400.4 2757.69,2400.4 2762.94,2395.15 2762.94,2367.35 2768.19,2362.1 2778.69,2362.1 2783.94,2367.35 2783.94,2395.15 2789.19,2400.4 2799.69,2400.4 2804.94,2395.15 2804.94,2367.35 2810.19,2362.1 2820.69,2362.1 2825.94,2367.35 2825.94,2395.15 2831.19,2400.4 2841.69,2400.4 2846.94,2395.15 2846.94,2367.35 2852.19,2362.1 2862.69,2362.1 2867.94,2367.35 2867.94,2395.15 2873.19,2400.4 2883.69,2400.4 2888.94,2395.15 2888.94,2367.35 2894.19,2362.1 2904.69,2362.1 2909.94,2367.35 2909.94,2395.15 2915.19,2400.4 2925.69,2400.4 2930.94,2395.15 2930.94,2367.35 2936.19,2362.1 2946.69,2362.1 2951.94,2367.35 2951.94,2395.15 2957.19,2400.4 2967.69,2400.4 2972.94,2395.15 2972.94,2367.35 2978.19,2362.1 2988.69,2362.1 2993.94,2367.35 2993.94,2395.15 2999.19,2400.4 3009.69,2400.4 3014.94,2395.15 3014.94,2367.35 3020.19,2362.1 3030.69,2362.1 3035.94,2367.35 3035.94,2395.15 3041.19,2400.4 3051.69,2400.4 3056.94,2395.15 3056.94,2367.35 3062.19,2362.1 3072.69,2362.1 3077.94,2367.35 3077.94,2395.15 3083.19,2400.4 3093.69,2400.4 3098.94,2395.15 3098.94,2367.35 3104.19,2362.1 3187.9,2362.1 3280.94,2269.06 3280.94,2251.54 3364,2168.48 3364,2052 3373.5,2042.5 v3(3386.6,2042.5)
H_DDR1_CLK_N: R90.1 U13.AE21 U14.K7 U15.K7 | length 4395.4
  Layer 1 - Top Layer w4: 3293,2171.4 3293,2143.23 3295.28,2140.95 U13.AE21@3295.28,2107.09
  Layer 1 - Top Layer w4.05: v4(2082.02,1566.26) U15.K7@2097.76,1582.01 ; v4(2082.02,2126.26) U14.K7@2097.76,2142.01
  Layer 1 - Top Layer w4.4: U14.K7@2097.76,2142.01 2097.76,2168.56 2112.6,2183.4 2460.4,2183.4 2484.2,2207.2 2484.2,2264.6 2496.8,2277.2 2517.2,2277.2 2529.8,2264.6 2529.8,2183.2 2534.2,2178.8 2543.6,2178.8 2548,2183.2 2548,2323.2 2560.6,2335.8 2582.7,2335.8 2595.3,2323.2 2595.3,2179 2599.7,2174.6 2610,2174.6 2614.4,2179 2614.4,2323.2 2627,2335.8 2648,2335.8 2660.6,2323.2 2660.6,2187.9 2665,2183.5 2675.3,2183.5 2679.7,2187.9 2679.7,2322.8 2692.3,2335.4 2715.2,2335.4 2727.8,2322.8 2727.8,2198.1 2732.2,2193.7 2741.3,2193.7 2745.7,2198.1 2745.7,2319.9 2760,2334.2 2782.8,2334.2 2795.4,2321.6 2795.4,2099.7 2799.8,2095.3 2810.4,2095.3 2814.8,2099.7 2814.8,2147.92 2827.4,2160.52 2847.4,2160.52 2851.8,2164.92 2851.8,2173.72 2847.4,2178.12 2827.4,2178.12 2814.8,2190.72 2814.8,2211.12 2827.4,2223.72 2847.4,2223.72 2851.8,2228.12 2851.8,2236.92 2847.4,2241.32 2827.4,2241.32 2814.8,2253.92 2814.8,2310.8 2827.4,2323.4 2952.5,2323.4 2965.1,2310.8 2965.1,2292 2969.5,2287.6 2979.3,2287.6 2983.7,2292 2983.7,2310.8 2996.3,2323.4 3018.4,2323.4 3083.2,2258.6 3205.8,2258.6 3293,2171.4
  Layer 1 - Top Layer w5: R90.1@2385,1239.68 v1(2385,1270)
  Layer 3 - Signal / PWR w4.5: v4(2082.02,2126.26) 2097.28,2111 2124,2111 2131,2104 2131,2066.4 2154,2043.4 2154,2028.8 2121,1995.8 2121,1944.19 2136,1929.19 2136,1887.2 2175,1848.2 2175,1832 2138,1795 2138,1724.1 2090.54,1676.64 2090.54,1658.67 2114,1635.21 2114,1627.99 2082,1595.99 2082,1569.21 v4(2082.02,1566.26) 2097.28,1551 2124.2,1551 2138.24,1536.96 2138.24,1494.78 2185.5,1447.52 2185.5,1359.5 2250,1295 2360,1295 v1(2385,1270)
H_DDR1_CLK_P: R89.1 U13.AD21 U14.J7 U15.J7 | length 4402.1
  Layer 1 - Top Layer w4: 3280,2163.8 3280,2137.84 3282.59,2135.25 3282.59,2101.83 3295.28,2089.14 U13.AD21@3295.28,2081.5
  Layer 1 - Top Layer w4.05: v4(2113.51,1566.26) U15.J7@2129.25,1582.01 ; v4(2113.51,2126.26) U14.J7@2129.25,2142.01
  Layer 1 - Top Layer w4.4: U14.J7@2129.25,2142.01 2120.01,2142 2111.76,2150.25 2111.76,2162.76 2118.4,2169.4 2466.2,2169.4 2498.2,2201.4 2498.2,2258.8 2502.6,2263.2 2511.4,2263.2 2515.8,2258.8 2515.8,2177.4 2528.4,2164.8 2549.4,2164.8 2562,2177.4 2562,2317.4 2566.4,2321.8 2576.9,2321.8 2581.3,2317.4 2581.3,2173.2 2593.9,2160.6 2615.8,2160.6 2628.4,2173.2 2628.4,2317.4 2632.8,2321.8 2642.2,2321.8 2646.6,2317.4 2646.6,2182.1 2659.2,2169.5 2681.1,2169.5 2693.7,2182.1 2693.7,2317 2698.1,2321.4 2709.4,2321.4 2713.8,2317 2713.8,2192.3 2726.4,2179.7 2747.1,2179.7 2759.7,2192.3 2759.7,2314.1 2765.8,2320.2 2777,2320.2 2781.4,2315.8 2781.4,2093.9 2794,2081.3 2816.2,2081.3 2828.8,2093.9 2828.8,2142.12 2833.2,2146.52 2853.2,2146.52 2865.8,2159.12 2865.8,2179.52 2853.2,2192.12 2833.2,2192.12 2828.8,2196.52 2828.8,2205.32 2833.2,2209.72 2853.2,2209.72 2865.8,2222.32 2865.8,2242.72 2853.2,2255.32 2833.2,2255.32 2828.8,2259.72 2828.8,2305 2833.2,2309.4 2946.7,2309.4 2951.1,2305 2951.1,2286.2 2963.7,2273.6 2985.1,2273.6 2997.7,2286.2 2997.7,2305 3002.1,2309.4 3012.6,2309.4 3077.4,2244.6 3121.4,2244.6 3133,2233 3152.1,2233 3163.7,2244.6 3200,2244.6 3280,2164.6 3280,2163.8
  Layer 1 - Top Layer w5: R89.1@2420,1239.68 v1(2420,1270)
  Layer 3 - Signal / PWR w4.5: v4(2113.51,2126.26) 2129.74,2126.26 2145,2111 2145,2072.2 2168,2049.2 2168,2023 2135,1990 2135,1949.99 2150,1934.99 2150,1893 2189,1854 2189,1826.2 2152,1789.2 2152,1718.3 2104.54,1670.84 2104.54,1664.47 2128,1641.01 2128,1622.19 2096,1590.19 2096,1575.01 2104.75,1566.26 v4(2113.51,1566.26) 2128.74,1566.26 2152.24,1542.76 2152.24,1500.58 2199.5,1453.32 2199.5,1370.5 2260,1310 2380,1310 v1(2420,1270)
H_DDR1_CSN0: R63.1 U13.AC19 U14.L2 U15.L2 | length 4363.5
  Layer 1 - Top Layer w4: v4(2050.52,1755.22) U15.L2@2066.26,1739.49 ; 3333.7,2136 3333.7,2068.7 U13.AC19@3346.4,2056
  Layer 1 - Top Layer w5: v4(2050.52,2315.22) U14.L2@2066.26,2299.49 ; R63.1@2350,1239.68 v1(2350,1270) ; v1(3288,2349) 3288,2332 3277,2321 3277,2236.3 3333.7,2179.6 3333.7,2136
  Layer 3 - Signal / PWR w5.25: v4(2050.52,1755.22) 2066.39,1771.09 2066.39,1793.19 2075.55,1802.35 2097.65,1802.35 2128,1832.7 2128,1845.99 2078,1895.99 2078,1950 2092,1964 2092,2031.19 2066.39,2056.8 2066.39,2132.73 2075.55,2141.89 2122.14,2141.89 2124.25,2144 2127.01,2144 2141,2157.99 2141,2253.01 2128.01,2266 2074.99,2266 2066.3,2274.69 2066.3,2299.44 v4(2050.52,2315.22) 2050.52,2399.04 2056.5,2405.02 2056.5,2432.6 2071.8,2447.9 2203.5,2447.9 2212.8,2457.2 2212.8,2482.5 2222.6,2492.3 2291.63,2492.3 2296.88,2487.05 2296.88,2468.15 2302.13,2462.9 2312.63,2462.9 2317.88,2468.15 2317.88,2487.05 2323.13,2492.3 2441.84,2492.3 2447.09,2487.05 2447.09,2462.55 2452.34,2457.3 2462.84,2457.3 2468.09,2462.55 2468.09,2487.05 2473.34,2492.3 2483.84,2492.3 2489.09,2487.05 2489.09,2462.55 2494.34,2457.3 2504.84,2457.3 2510.09,2462.55 2510.09,2487.05 2515.34,2492.3 2525.84,2492.3 2531.09,2487.05 2531.09,2462.55 2536.34,2457.3 2546.84,2457.3 2552.09,2462.55 2552.09,2487.05 2557.34,2492.3 2567.84,2492.3 2573.09,2487.05 2573.09,2462.55 2578.34,2457.3 2588.84,2457.3 2594.09,2462.55 2594.09,2487.05 2599.34,2492.3 2609.84,2492.3 2615.09,2487.05 2615.09,2462.55 2620.34,2457.3 2630.84,2457.3 2636.09,2462.55 2636.09,2487.05 2641.34,2492.3 2651.84,2492.3 2657.09,2487.05 2657.09,2462.55 2662.34,2457.3 2672.84,2457.3 2678.09,2462.55 2678.09,2487.05 2683.34,2492.3 2710.2,2492.3 2715.45,2497.55 2715.45,2517.85 2720.7,2523.1 2731.2,2523.1 2736.45,2517.85 2736.45,2497.55 2741.7,2492.3 2752.2,2492.3 2757.45,2497.55 2757.45,2517.85 2762.7,2523.1 2773.2,2523.1 2778.45,2517.85 2778.45,2497.55 2783.7,2492.3 2794.2,2492.3 2799.45,2497.55 2799.45,2517.85 2804.7,2523.1 2815.2,2523.1 2820.45,2517.85 2820.45,2497.55 2825.7,2492.3 2836.2,2492.3 2841.45,2497.55 2841.45,2517.85 2846.7,2523.1 2857.2,2523.1 2862.45,2517.85 2862.45,2497.55 2867.7,2492.3 2878.94,2492.3 2884.19,2487.05 2884.19,2460.65 2889.44,2455.4 2899.94,2455.4 2905.19,2460.65 2905.19,2487.05 2910.44,2492.3 2920.94,2492.3 2926.19,2487.05 2926.19,2460.65 2931.44,2455.4 2941.94,2455.4 2947.19,2460.65 2947.19,2487.05 2952.44,2492.3 2962.94,2492.3 2968.19,2487.05 2968.19,2460.65 2973.44,2455.4 2983.94,2455.4 2989.19,2460.65 2989.19,2487.05 2994.44,2492.3 3004.94,2492.3 3010.19,2487.05 3010.19,2460.65 3015.44,2455.4 3025.94,2455.4 3031.19,2460.65 3031.19,2487.05 3036.44,2492.3 3078.6,2492.3 3145.85,2425.05 3235.96,2425.05 3254,2407.01 3254,2370 3259,2365 3271.75,2365 3277,2370.25 3277,2396.75 3282.25,2402 3305.5,2402 3310.75,2396.75 3310.75,2354.25 3305.5,2349 v1(3288,2349)
  Layer 6 - Bottom Layer w5: v4(2050.52,1755.22) 2050.52,1745.66 2035,1730.14 2035,1678 1972.03,1615.03 1972.03,1488.97 1994,1467 2006.34,1467 2116.12,1357.22 2172.78,1357.22 2235,1295 2325,1295 v1(2350,1270)
H_DDR1_D0: U13.AA23 U14.H7 | length 1301.6
  Layer 1 - Top Layer w4: U14.H7@2160.75,2142 v4(2176.49,2126.26) ; U13.AA23@3244,2004.8 U13.AA23@3244.09,2004.72 v3(3257.5,1996.3)
  Layer 3 - Signal / PWR w5.2: v3@3257.2,1996 v3(3257.5,1996.3)
  Layer 3 - Signal / PWR w5.25: v4(2176.49,2126.26) 2192.2,2110.55 2192.2,2086.5 2199.6,2079.1 2453.41,2079.1 2485.13,2110.82 2501.18,2110.82 2534,2078 2543,2078 2578,2113 2599,2113 2634,2078 2649,2078 2686,2115 2710.01,2115 2745.84,2079.17 2808.83,2079.17 2848.9,2039.1 2991.1,2039.1 3025,2073 3052.35,2073 3086.35,2039 3198.65,2039 3241.35,1996.3 v3(3257.5,1996.3)
H_DDR1_D1: U13.AC24 U14.F8 | length 1339.1
  Layer 1 - Top Layer w4: U14.F8@2223.74,2110.51 v4(2239.48,2094.77) ; 3160.41,2065.91 3163.1,2068.6 3198.17,2068.6 3205.6,2061.17 3205.6,2061.01 3210.7,2055.91
  Layer 1 - Top Layer w4.05: 3210.7,2055.91 U13.AC24@3218.5,2055.91
  Layer 1 - Top Layer w5: v1(2906,2058) 2920,2058 2934.41,2072.41 2949.58,2072.41 2956.08,2065.91 3160.41,2065.91
  Layer 3 - Signal / PWR w5.25: v4(2239.48,2094.77) 2255.11,2110.4 2417.24,2110.4 2436.84,2130 2722,2130 2756.76,2095.24 2861.13,2095.24 2866.33,2100.44 2866.33,2107.8 2861.13,2113 2769.2,2113 2764,2118.2 2764,2125.56 2769.2,2130.76 2894.01,2130.76 2906,2118.77 v1(2906,2058)
H_DDR1_D2: U13.AB24 U14.F7 | length 1218.5
  Layer 1 - Top Layer w4: U14.F7@2223.74,2142.01 v4(2239.48,2126.26) ; 3163,2043 3205.81,2043 U13.AB24@3218.5,2030.32
  Layer 1 - Top Layer w5: v1(2858,2056) 2875,2039 2960.9,2039 2964.9,2043 3163,2043
  Layer 4 - Signal / PWR w5.25: v4(2239.48,2126.26) 2239.48,2162.48 2299,2222 2568.75,2222 2573.95,2216.8 2573.95,2209.2 2579.15,2204 2589.55,2204 2594.75,2209.2 2594.75,2216.8 2599.95,2222 2610.35,2222 2615.55,2216.8 2615.55,2196.2 2620.75,2191 2631.15,2191 2636.35,2196.2 2636.35,2216.8 2641.55,2222 2692,2222 v1(2858,2056)
H_DDR1_D3: U13.AD24 U14.H8 | length 1351.7
  Layer 1 - Top Layer w4: U14.H8@2160.75,2110.51 v4(2176.49,2094.77) ; 3194,2136 3205.7,2124.3 3205.7,2100.7 3218.5,2087.9 U13.AD24@3218.5,2081.5
  Layer 1 - Top Layer w5: v1(2918,2182) 2918,2153 2974.28,2096.72 3105.72,2096.72 3150,2141 3189,2141 3194,2136
  Layer 3 - Signal / PWR w5.25: v4(2176.49,2094.77) 2160,2111.26 2160,2128 2157.39,2130.61 2157.39,2210.79 2165.6,2219 2193,2219 2245.5,2166.5 2902.5,2166.5 v1(2918,2182)
H_DDR1_D4: U13.AB23 U14.E3 | length 1308.2
  Layer 1 - Top Layer w4: U14.E3@2255.24,2267.99 v4(2270.98,2283.73) ; U13.AB23@3244,2030.4 U13.AB23@3244.09,2030.32 v3(3256.66,2020.32)
  Layer 3 - Signal / PWR w5.25: v4(2270.98,2283.73) 2286.65,2299.4 2808.6,2299.4 2850,2258 2913,2258 2948,2293 3211,2293 3218,2286 3218,2261 3242,2237 3242,2034.98 v3(3256.66,2020.32)
H_DDR1_D5: U13.AC23 U14.H3 | length 1362.2
  Layer 1 - Top Layer w4: U14.H3@2160.75,2267.99 v4(2176.49,2283.73) ; 3153.6,2086.84 3161.06,2094.3
  Layer 1 - Top Layer w4.05: 3161.06,2094.3 3198.81,2094.3 3205.7,2087.41 3205.7,2076.11 3213.11,2068.7 3231.3,2068.7 U13.AC23@3244.09,2055.91
  Layer 1 - Top Layer w5: v1(2882,2232) 2882,2140 2929.59,2092.41 2962.39,2092.41 2968.08,2086.72 3153.48,2086.72 3153.6,2086.84
  Layer 3 - Signal / PWR w5.25: v4(2176.49,2283.73) 2192.16,2299.4 2247.6,2299.4 2255.3,2291.7 2255.3,2273.7 2267,2262 2463,2262 2478,2277 2804.86,2277 2813,2268.86 2813,2261.5 2804.78,2253.28 2786.48,2253.28 2781,2247.8 2781,2236 2785,2232 v1(2882,2232)
H_DDR1_D6: U13.AD23 U14.F2 | length 1364.4
  Layer 1 - Top Layer w4: U14.F2@2223.74,2299.49 v4(2239.48,2315.22) ; 3231.2,2136 3231.2,2094.39 U13.AD23@3244.09,2081.5
  Layer 1 - Top Layer w5: v1(2845,2293) 2902,2293 2964,2231 3079,2231 3145.76,2164.24 3206.56,2164.24 3231.2,2139.6 3231.2,2136
  Layer 3 - Signal / PWR w5.25: v4(2239.48,2315.22) 2255.26,2331 2486,2331 2496,2341 2496,2348.8 2503,2355.8 2914.8,2355.8 2920,2350.6 2920,2337.2 2914.8,2332 2853,2332 2845,2324 v1(2845,2293)
H_DDR1_D7: U13.AE24 U14.G2 | length 1358.1
  Layer 1 - Top Layer w4: U14.G2@2192.24,2299.49 v4(2207.98,2315.22) ; U13.AE24@3218.5,2107.09 3218.5,2136
  Layer 1 - Top Layer w5: v1(2893.5,2275.5) 2952.59,2216.41 3074.43,2216.41 3139.84,2151 3204,2151 3218.5,2136.5 3218.5,2136
  Layer 3 - Signal / PWR w5.25: v4(2207.98,2315.22) 2223.7,2330.94 2223.7,2356.7 2235.2,2368.2 2947.6,2368.2 2955,2360.8 2955,2325.2 2949.8,2320 2905.5,2320 2893.5,2308 v1(2893.5,2275.5)
H_DDR1_D8: U13.AA24 U14.A2 | length 1231.9
  Layer 1 - Top Layer w4: U14.A2@2381.22,2299.49 v4(2396.96,2315.22) ; 3163,2017.6 3205.62,2017.6 U13.AA24@3218.5,2004.72
  Layer 1 - Top Layer w5: v1(3019,2013) 3034.4,2013 3039,2017.6 3163,2017.6
  Layer 4 - Signal / PWR w5.25: v4(2396.96,2315.22) 2803.8,2315.22 2809,2310.02 2809,2288.2 2814.2,2283 2821.8,2283 2827,2288.2 2827,2310.02 2832.2,2315.22 2861.78,2315.22 2873,2304 2873,2266 2885,2254 2902,2254 2909,2247 2909,2223 2898,2212 2898,2178 2913,2163 2928.8,2163 2934,2157.8 2934,2142 2941,2135 2964,2135 2970,2129 2970,2110 2980.1,2099.9 3017.3,2099.9 3024,2093.2 3024,2083 3018.8,2077.8 2994.2,2077.8 2989,2072.6 2989,2062.2 2994.2,2057 3013.8,2057 3019,2051.8 v1(3019,2013)
H_DDR1_D9: U13.W25 U14.B8 | length 1319.7
  Layer 1 - Top Layer w4: U14.B8@2349.72,2110.51 v4(2365.46,2094.77)
  Layer 1 - Top Layer w4.05: 3163,1953.54 U13.W25@3192.91,1953.54
  Layer 1 - Top Layer w5: v1(2614,2060) 2634,2060 2651,2077 2651,2110 2657,2116 2667,2116 2672,2111 2672,2038 2677,2033 2687,2033 2693.6,2039.6 2693.6,2133.4 2706.6,2146.4 2731.6,2146.4 2743.7,2134.3 2743.7,2046.7 2732,2035 2732,1944 2754,1922 2988,1922 3019.54,1953.54 3163,1953.54
  Layer 4 - Signal / PWR w5.25: v4(2365.46,2094.77) 2381.23,2079 2485,2079 2504,2060 v1(2614,2060)
H_DDR1_D10: U13.Y23 U14.A7 | length 1535.1
  Layer 1 - Top Layer w4: U14.A7@2381.22,2142.01 v4(2396.96,2126.26) ; 3205.74,1966.3 3231.26,1966.3 U13.Y23@3244.09,1979.13
  Layer 1 - Top Layer w4.05: 3163,1966.3 3205.74,1966.3
  Layer 1 - Top Layer w5: v4(2396.96,2126.26) 2400.22,2123 2430,2123 2449,2142 2485.23,2142 2490.23,2137 2490.23,2090 2495.23,2085 2503,2085 2508,2090 2508,2139.77 2515.23,2147 2525.23,2147 2530.23,2142 2530.23,2090 2535.23,2085 2545.23,2085 2550.23,2090 2550.23,2141 2555.23,2146 2565.23,2146 2570.23,2141 2570.23,2088 2575.23,2083 2582.31,2083 2587.31,2088 2587.31,2138.08 2595.23,2146 2605.23,2146 2610.23,2141 2610.23,2087 2615.23,2082 2625.23,2082 2630.23,2087 2630.23,2137 2635.23,2142 2672.4,2142 2695.2,2164.8 2733.3,2164.8 2760.9,2137.2 2760.9,2053.6 2771.5,2043 2771.5,1997.5 2788,1981 2881,1981 2888,1974 2888,1947 2900,1935 2980.99,1935 3010.48,1964.49 3069,1964.49 3070.81,1966.3 3163,1966.3
H_DDR1_D11: U13.AD25 U14.C8 | length 1254.2
  Layer 1 - Top Layer w4: U14.C8@2318.23,2110.51 v4(2333.97,2094.77) ; 3158.2,2076.7 3163,2081.5 U13.AD25@3192.91,2081.5
  Layer 1 - Top Layer w5: v1(2804,2056) 2824.99,2056 2851.4,2082.41 2954.96,2082.41 2960.67,2076.7 3158.2,2076.7
  Layer 4 - Signal / PWR w5.25: v4(2333.97,2094.77) 2318.34,2110.4 2293.7,2110.4 2286.8,2117.3 2286.8,2187.8 2306,2207 2448,2207 2477,2178 2696,2178 2705.91,2168.09 2705.91,2160.73 2684.27,2139.09 2684.27,2131.73 2691.62,2124.38 2698.98,2124.38 2720.62,2146.02 2734.98,2146.02 2746,2135 2746,2061.2 2751.2,2056 v1(2804,2056)
H_DDR1_D12: U13.AC25 U14.C3 | length 1237.8
  Layer 1 - Top Layer w4: U14.C3@2318.23,2267.99 v4(2333.97,2283.73) ; 3163,2055.91 U13.AC25@3192.91,2055.91
  Layer 1 - Top Layer w5: v1(2942,2055.91) 3163,2055.91
  Layer 4 - Signal / PWR w5.25: v4(2333.97,2283.73) 2333.97,2262.2 2339.17,2257 2617,2257 2647,2287 2753,2287 2783,2257 2820,2257 2831,2246 2831,2175 2835,2171 2847,2171 2850,2174 2850,2201 2854.5,2205.5 2864.49,2205.5 2869.46,2200.53 2869.46,2131.53 2887.11,2113.88 2887.11,2090.2 2892.31,2085 2901,2085 2906.2,2090.2 2906.2,2109.09 2913.11,2116 2920.49,2116 2928,2108.49 2928,2095.19 2933.2,2089.99 2953,2089.99 2958.36,2084.63 2958.36,2072.27 v1(2942,2055.91)
H_DDR1_D13: U13.AB25 U14.D7 | length 1239.6
  Layer 1 - Top Layer w4: U14.D7@2286.73,2142.01 v4(2302.47,2126.26) ; 3163,2030.31 U13.AB25@3192.91,2030.32
  Layer 1 - Top Layer w5: v1(2935.8,2021.4) 2936.4,2021.4 2941,2026 2988.69,2026 2993,2030.31 3163,2030.31
  Layer 4 - Signal / PWR w5.25: v4(2302.47,2126.26) 2302.47,2140.48 2312.29,2150.3 2312.29,2163.7 2302.47,2173.52 2302.47,2183.46 2314.01,2195 2324,2195 2338,2181 2355,2181 2369,2195 2383,2195 2395,2183 2416,2183 2428,2195 2439,2195 2451,2183 2451,2169.2 2456.2,2164 2605,2164 2674,2095 2674,2041 2656,2023 2656,2013.2 2661.2,2008 2690.8,2008 2696,2013.2 2696,2037.68 2701.32,2043 2711,2043 2715.5,2038.5 2715.5,2021.5 2720,2017 2731,2017 2737,2023 2737,2030 2749.16,2042.16 2759.52,2042.16 2776.68,2025 2915,2025 2918.6,2021.4 v1(2935.8,2021.4)
H_DDR1_D14: U13.AA25 U14.A3 | length 1237.9
  Layer 1 - Top Layer w4: U14.A3@2381.22,2267.99 v4(2396.96,2283.73) ; 3163,2004.72 U13.AA25@3192.91,2004.72
  Layer 1 - Top Layer w5: v1(2990,2009) 3002.5,1996.5 3040.5,1996.5 3048.72,2004.72 3163,2004.72
  Layer 4 - Signal / PWR w5.25: v4(2396.96,2283.73) 2413.23,2300 2425.33,2300 2430.53,2294.8 2430.53,2280.2 2435.73,2275 2446.13,2275 2451.33,2280.2 2451.33,2294.8 2456.53,2300 2466.93,2300 2472.13,2294.8 2472.13,2280.2 2477.33,2275 2487.73,2275 2492.93,2280.2 2492.93,2294.8 2498.13,2300 2508.53,2300 2513.73,2294.8 2513.73,2280.2 2518.93,2275 2529.33,2275 2534.53,2280.2 2534.53,2294.8 2539.73,2300 2550.13,2300 2555.33,2294.8 2555.33,2280.2 2560.53,2275 2570.93,2275 2576.13,2280.2 2576.13,2294.8 2581.33,2300 2591.73,2300 2596.93,2294.8 2596.93,2280.2 2602.13,2275 2612.53,2275 2617.73,2280.2 2617.73,2294.8 2622.93,2300 2785,2300 2793,2292 2793,2276.2 2798.2,2271 2851,2271 2859,2263 2859,2230 2886,2203 2886,2150 2908.5,2127.5 2931.5,2127.5 2975,2084 2975,2053 2990,2038 v1(2990,2009)
H_DDR1_D15: U13.W24 U14.C2 | length 1235.2
  Layer 1 - Top Layer w4: U14.C2@2318.23,2299.49 v4(2333.97,2315.22) ; 3163,1940.7 3205.75,1940.7 3205.75,1940.79 U13.W24@3218.5,1953.54
  Layer 1 - Top Layer w5: v1(3029,1935.7) 3045.7,1935.7 3050.7,1940.7 3163,1940.7
  Layer 4 - Signal / PWR w5.25: v4(2333.97,2315.22) 2349.65,2330.9 2867.1,2330.9 2925,2273 2925,2212 3046,2091 3046,1952.7 v1(3029,1935.7)
H_DDR1_D16: U13.W23 U15.F8 | length 1550.4
  Layer 1 - Top Layer w4: U15.F8@2223.74,1550.51 v4(2239.48,1534.77) ; v3(3234.3,1940) U13.W23@3244.09,1953.54
  Layer 4 - Signal / PWR w5.25: v4(2239.48,1534.77) 2223.85,1550.4 2169.2,1550.4 2158,1561.6 2158,1602 2140,1620 2140,1805 2227.4,1892.4 2405.89,1892.4 2433.49,1920 2672,1920 2680,1928 2990,1928 3011.4,1906.6 3056.2,1906.6 3089.6,1940 v3(3234.3,1940)
H_DDR1_D17: U13.U25 U15.H8 | length 1736.5
  Layer 1 - Top Layer w4: U15.H8@2160.75,1550.51 v4(2176.49,1534.77) ; 3163,1902.36 U13.U25@3192.91,1902.36
  Layer 1 - Top Layer w5: v1(2785.2,1766.24) 2785.2,1854 2790.2,1859 2829.16,1859 2840,1848.16 2859.68,1848.16 2883.22,1871.7 3036.67,1871.7 3037.03,1871.34 3050.71,1871.34 3051.07,1871.7 3085.7,1871.7 3116.36,1902.36 3163,1902.36
  Layer 3 - Signal / PWR w5.25: v4(2176.49,1534.77) 2192.3,1550.58 2192.3,1576.54 2215,1599.24 2215,1678 2209,1684 2197,1684 2191,1678 2191,1595.25 2184.75,1589 2172.25,1589 2166,1595.25 2166,1688 2179,1701 2298,1701 2316,1683 2435,1683 2445,1693 2488,1693 2504,1709 2504,1734 2512,1742 2535,1742 2543.5,1733.5 2543.5,1717 2554.5,1706 2574.88,1706 2583,1714.12 2583,1737 2590,1744 2718,1744 2727,1735 2727,1716 2738,1705 2755,1705 2766.8,1716.8 2766.8,1747.84 v1(2785.2,1766.24)
H_DDR1_D18: U13.U24 U15.F7 | length 1754.1
  Layer 1 - Top Layer w4: U15.F7@2223.74,1582.01 v4(2239.48,1566.26) ; 3163,1889.5 3205.71,1889.5 3205.77,1889.56 3205.77,1889.63 U13.U24@3218.5,1902.36
  Layer 1 - Top Layer w5: v1(2802,1734.24) 2802,1771 2844,1813 2844,1819 2840,1823 2828,1823 2810,1805 2801,1805 2798,1808 2798,1840 2806,1848 2821.16,1848 2831,1838.16 2869.16,1838.16 2892.7,1861.7 3032.52,1861.7 3032.88,1861.34 3054.86,1861.34 3055.22,1861.7 3094.71,1861.7 3122.51,1889.5 3163,1889.5
  Layer 3 - Signal / PWR w5.25: v4(2239.48,1566.26) 2223.7,1550.48 2223.7,1490.3 2235,1479 2310,1479 2318,1487 2318,1496.7 2318.1,1496.8 2318.1,1572.73 2318,1572.83 2318,1580.37 2310,1588.37 2310,1641 2325,1656 2455,1656 2468,1669 2512,1669 2523,1680 2609.8,1680 2615,1674.8 2615,1662 2611,1658 2557,1658 2549.18,1650.18 2549.18,1642.82 2557,1635 2695,1635 2704,1644 2768,1644 2784,1660 2784,1694.39 2795.23,1705.62 2795.23,1727.47 v1(2802,1734.24)
H_DDR1_D19: U13.W21 U15.F2 | length 1687.1
  Layer 1 - Top Layer w4: U15.F2@2223.74,1739.49 v4(2239.48,1755.22) ; v3(3285.1,1940.7) U13.W21@3295.28,1953.54
  Layer 3 - Signal / PWR w5.25: v4(2239.48,1755.22) 2223.61,1771.09 2223.61,1803.61 2245,1825 2245,1852.7 2266,1873.7 2266,1939 2297,1970 2379,1970 2409.6,2000.6 2422.72,2000.6 2427.92,1995.4 2427.92,1982.2 2433.12,1977 2443.52,1977 2448.72,1982.2 2448.72,1995.4 2453.92,2000.6 2464.32,2000.6 2469.52,1995.4 2469.52,1982.2 2474.72,1977 2485.12,1977 2490.32,1982.2 2490.32,1995.4 2497.92,2003 2633,2003 2657.7,1978.3 2955.7,1978.3 2976,1958 2997.12,1958 3002.32,1963.2 3002.32,1988.8 3007.52,1994 3017.92,1994 3023.12,1988.8 3023.12,1963.2 3028.32,1958 3038.72,1958 3043.92,1963.2 3043.92,1988.8 3049.12,1994 3059.52,1994 3064.72,1988.8 3064.72,1963.2 3069.92,1958 3080.32,1958 3085.52,1963.2 3085.52,1988.8 3090.72,1994 3101.12,1994 3106.32,1988.8 3106.32,1963.2 3111.52,1958 3121.92,1958 3127.12,1963.2 3127.12,1988.8 3132.32,1994 3142.72,1994 3147.92,1988.8 3147.92,1963.2 3153.12,1958 3163.52,1958 3168.72,1963.2 3168.72,1988.8 3173.92,1994 3184.32,1994 3189.52,1988.8 3189.52,1963.2 3194.72,1958 3267.8,1958 v3(3285.1,1940.7)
